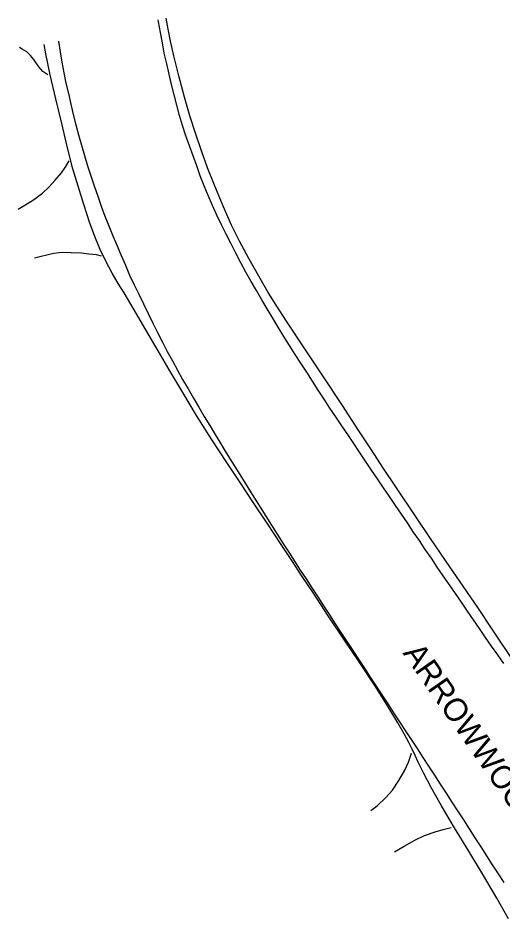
# Model space of a CAD drawing. Extents: x 1948091 to 1975253, y 787267 to 823306.
# Drawn here: x 1971297.2 to 1971410.9, y 796136.5 to 796347.8 of the extents above; entities that cross this region are included whole.
import ezdxf

# ---------------------------------------------------------------- set-up
doc = ezdxf.new("R2010")
doc.units = 0
for name, color, linetype in [('RD_EX_Pavement_Markings', 7, 'Continuous'), ('RD_EX_Road', 7, 'Continuous'), ('RD_TX_RoadID', 7, 'Continuous')]:
    doc.layers.add(name, color=color, linetype=linetype)

msp = doc.modelspace()

# ---------------------------------------------------------------- linework, layer by layer
at = {"layer": 'RD_EX_Pavement_Markings'}
for points in [[(1971411.07, 796196.38), (1971409.65, 796198.44), (1971408.23, 796200.49), (1971406.82, 796202.55), (1971405.4, 796204.61), (1971403.98, 796206.67), (1971402.56, 796208.73), (1971401.14, 796210.79), (1971399.73, 796212.85), (1971398.31, 796214.91), (1971396.9, 796216.97), (1971395.49, 796219.04), (1971394.09, 796221.11), (1971392.68, 796223.17), (1971391.28, 796225.24), (1971389.87, 796227.31), (1971388.47, 796229.38), (1971387.06, 796231.45), (1971385.66, 796233.51), (1971384.25, 796235.58), (1971382.85, 796237.65), (1971381.45, 796239.72), (1971380.06, 796241.8), (1971378.67, 796243.88), (1971377.28, 796245.96), (1971375.89, 796248.03), (1971374.5, 796250.11), (1971373.11, 796252.19), (1971371.72, 796254.27), (1971370.33, 796256.34), (1971368.94, 796258.42), (1971367.57, 796260.51), (1971366.22, 796262.62), (1971364.87, 796264.72), (1971363.52, 796266.83), (1971362.17, 796268.93), (1971360.82, 796271.04), (1971359.48, 796273.15), (1971358.2, 796275.29), (1971356.91, 796277.43), (1971355.62, 796279.58), (1971354.36, 796281.73), (1971353.11, 796283.9), (1971351.86, 796286.06), (1971350.61, 796288.23), (1971349.45, 796290.44), (1971348.3, 796292.66), (1971347.14, 796294.88), (1971345.99, 796297.1), (1971344.89, 796299.34), (1971343.79, 796301.59), (1971342.77, 796303.87), (1971341.8, 796306.17), (1971340.82, 796308.47), (1971339.94, 796310.81), (1971339.09, 796313.16), (1971338.23, 796315.51), (1971337.38, 796317.86), (1971336.57, 796320.22), (1971335.76, 796322.58), (1971335.08, 796324.99), (1971334.42, 796327.4), (1971333.8, 796329.82), (1971333.22, 796332.25), (1971332.63, 796334.68), (1971332.05, 796337.12), (1971331.49, 796339.55), (1971331.04, 796342.01), (1971330.58, 796344.47), (1971330.13, 796346.93), (1971330.04, 796347.42)], [(1971306.7, 796342.37), (1971307.09, 796339.91), (1971307.51, 796337.44), (1971307.92, 796334.97), (1971308.45, 796332.53), (1971309.01, 796330.09), (1971309.56, 796327.66), (1971310.17, 796325.23), (1971310.78, 796322.81), (1971311.4, 796320.39), (1971312.08, 796317.98), (1971312.77, 796315.58), (1971313.5, 796313.19), (1971314.29, 796310.81), (1971315.08, 796308.44), (1971315.88, 796306.07), (1971316.72, 796303.72), (1971317.57, 796301.37), (1971318.52, 796299.06), (1971319.46, 796296.74), (1971320.41, 796294.43), (1971321.4, 796292.13), (1971322.38, 796289.83), (1971323.37, 796287.54), (1971324.42, 796285.27), (1971325.51, 796283.02), (1971326.6, 796280.77), (1971327.7, 796278.52), (1971328.79, 796276.27), (1971329.91, 796274.04), (1971331.04, 796271.81), (1971332.19, 796269.59), (1971333.39, 796267.4), (1971334.6, 796265.21), (1971335.8, 796263.02), (1971337.06, 796260.85), (1971338.31, 796258.69), (1971339.57, 796256.53), (1971340.85, 796254.38), (1971342.14, 796252.25), (1971343.44, 796250.11), (1971344.73, 796247.97), (1971346.03, 796245.83), (1971347.35, 796243.71), (1971348.68, 796241.59), (1971350, 796239.47), (1971351.33, 796237.35), (1971352.66, 796235.23), (1971353.98, 796233.11), (1971355.3, 796230.99), (1971356.62, 796228.87), (1971357.95, 796226.75), (1971359.29, 796224.64), (1971360.65, 796222.54), (1971362.01, 796220.45), (1971363.38, 796218.35), (1971364.74, 796216.25), (1971366.1, 796214.16), (1971367.46, 796212.06), (1971368.82, 796209.96), (1971370.18, 796207.86), (1971371.54, 796205.76), (1971372.9, 796203.67), (1971374.27, 796201.58), (1971375.65, 796199.49), (1971377.03, 796197.41), (1971378.4, 796195.32), (1971379.78, 796193.23), (1971381.15, 796191.14), (1971382.52, 796189.05), (1971383.89, 796186.96), (1971385.26, 796184.86), (1971386.62, 796182.77), (1971387.99, 796180.68), (1971389.36, 796178.59), (1971390.73, 796176.5), (1971392.09, 796174.4), (1971393.45, 796172.3), (1971394.81, 796170.2), (1971396.17, 796168.11), (1971397.53, 796166.01), (1971398.89, 796163.91), (1971400.25, 796161.82), (1971401.6, 796159.71), (1971402.96, 796157.61), (1971404.32, 796155.51), (1971405.67, 796153.41), (1971407.03, 796151.31), (1971408.38, 796149.21), (1971409.74, 796147.11), (1971411.09, 796145.01)]]:
    msp.add_lwpolyline(points, dxfattribs=at)
at = {"layer": 'RD_EX_Road'}
for points in [[(1971413.91, 796196.2), (1971408.38, 796204.51), (1971405.15, 796209.3), (1971401.55, 796214.59), (1971397.58, 796220.38), (1971393.73, 796225.99), (1971390.5, 796230.73), (1971385.9, 796237.61), (1971382.75, 796242.42), (1971380.05, 796246.54), (1971377.11, 796251.03), (1971373.23, 796256.92), (1971368.78, 796263.66), (1971364.11, 796270.68), (1971360.11, 796276.71), (1971357.68, 796280.47), (1971355.84, 796283.47), (1971353.63, 796287.25), (1971351.31, 796291.39), (1971349.15, 796295.47), (1971347.28, 796299.24), (1971345.83, 796302.47), (1971344.52, 796305.59), (1971343.11, 796308.99), (1971341.65, 796312.69), (1971340.26, 796316.47), (1971338.77, 796320.84), (1971337.48, 796324.92), (1971336.22, 796329.28), (1971334.89, 796334.27), (1971333.72, 796338.96), (1971332.93, 796342.42), (1971332.38, 796345.2), (1971331.96, 796347.83)], [(1971304.16, 796334.53), (1971303.01, 796335.28), (1971302.11, 796336.38), (1971300.94, 796338.12), (1971300.1, 796339.03), (1971299.24, 796339.92), (1971298.17, 796340.54), (1971297.54, 796340.91)], [(1971412.18, 796136.49), (1971409.46, 796141.39), (1971406.34, 796146.7), (1971402.85, 796152.4), (1971399.52, 796157.89), (1971396.48, 796163.01), (1971394.04, 796167.34), (1971392.22, 796170.79), (1971391, 796173.24), (1971390.3, 796174.82), (1971389.62, 796176.31), (1971388.84, 796177.9), (1971387.76, 796179.9), (1971386.26, 796182.48), (1971383.94, 796186.27), (1971380.81, 796191.24), (1971377.33, 796196.59), (1971373.61, 796202.13), (1971369.94, 796207.63), (1971366.44, 796212.91), (1971363.69, 796217.09), (1971361.58, 796220.32), (1971358.91, 796224.37), (1971355.6, 796229.33), (1971352.43, 796234.11), (1971349.44, 796238.63), (1971346.14, 796243.6), (1971342.53, 796249.07), (1971339.06, 796254.58), (1971335.81, 796260.02), (1971332.82, 796265.06), (1971330.02, 796269.77), (1971327.13, 796274.71), (1971324.21, 796279.74), (1971322.06, 796283.35), (1971320.7, 796285.58), (1971319.31, 796288), (1971317.81, 796290.81), (1971316.49, 796293.51), (1971315.35, 796296.17), (1971314.06, 796299.7), (1971312.63, 796304.09), (1971311.29, 796308.36), (1971310.07, 796312.47), (1971308.8, 796317.38), (1971307.46, 796323.11), (1971306.08, 796328.88), (1971304.73, 796334.48), (1971303.69, 796339.44), (1971303.31, 796341.64)], [(1971297.21, 796302.97), (1971300.58, 796305.04), (1971302.92, 796306.74), (1971304.52, 796308.22), (1971305.86, 796309.71), (1971307.39, 796311.54), (1971308.44, 796312.97), (1971309.21, 796314.31)], [(1971301.07, 796291.54), (1971305.55, 796292.71), (1971307.57, 796292.88), (1971309.67, 796292.86), (1971312.11, 796292.72), (1971313.84, 796292.52), (1971315.5, 796292.32), (1971316.68, 796292.07)], [(1971379.93, 796161.93), (1971381.38, 796163.05), (1971383.41, 796165.02), (1971384.98, 796166.73), (1971386.5, 796168.95), (1971387.89, 796171.39), (1971388.71, 796173.26), (1971389.46, 796175.41)], [(1971385.45, 796152.21), (1971387.75, 796153.54), (1971390.26, 796154.96), (1971392.51, 796156.04), (1971394.97, 796156.94), (1971396.88, 796157.5), (1971398.7, 796157.93)]]:
    msp.add_lwpolyline(points, dxfattribs=at)

# ---------------------------------------------------------------- texts
at = {"layer": 'RD_TX_RoadID'}
msp.add_text('ARROWWOOD RD', height=5.4, rotation=304.8214, dxfattribs=at).set_placement((1971387.29, 796198.85))

doc.saveas('drawing.dxf')
